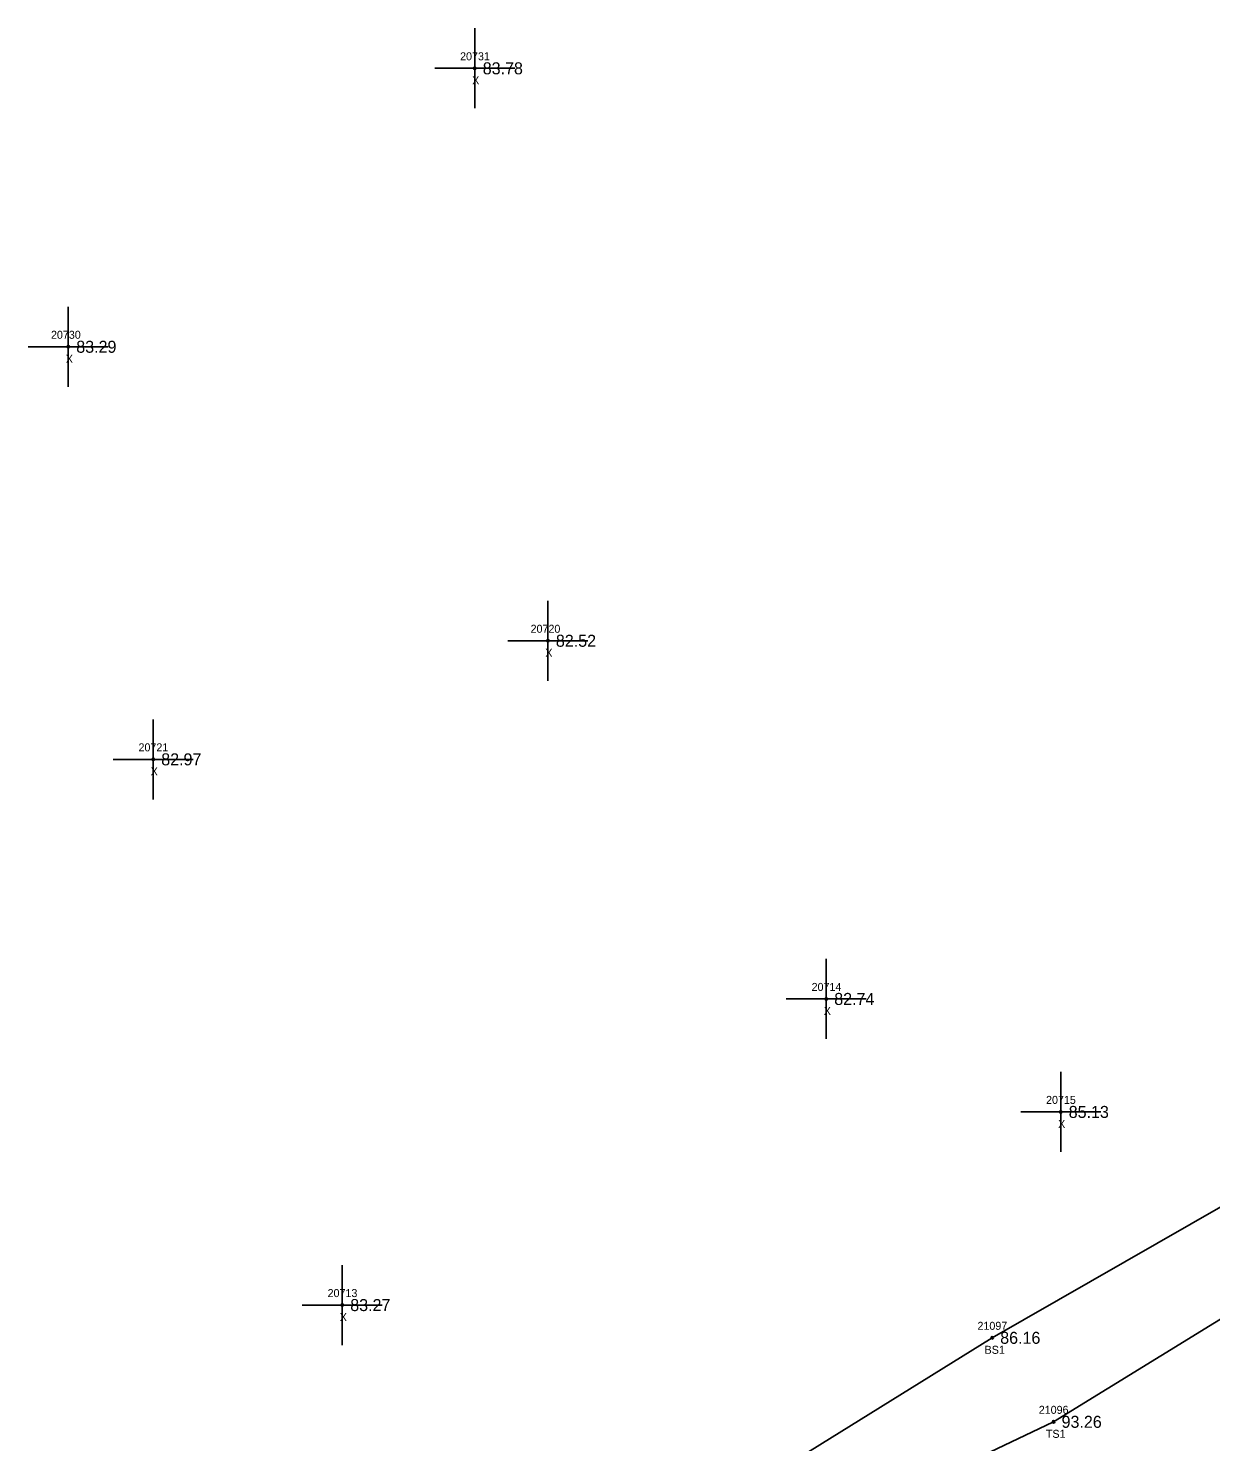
# Model space of a CAD drawing. Extents: x 2530197 to 2532051, y 935230 to 936631.
# Drawn here: x 2531110.5 to 2531258.3, y 936173.5 to 936350.2 of the extents above; entities that cross this region are included whole.
import ezdxf

# ---------------------------------------------------------------- set-up
doc = ezdxf.new("R2010")
doc.units = 0
for name, color, linetype in [('RD_DTM_BkLn2', 7, 'Continuous'), ('RD_DTM_BkLn_txCode', 7, 'Continuous'), ('RD_EX_Misc', 7, 'Continuous'), ('RD_EX_Misc_txCode', 7, 'Continuous'), ('RD_EX_TX_Misc_ELEV', 7, 'Continuous'), ('RD_SMD_Locator', 7, 'Continuous')]:
    doc.layers.add(name, color=color, linetype=linetype)

msp = doc.modelspace()

# ---------------------------------------------------------------- linework, layer by layer
at = {"layer": 'RD_DTM_BkLn2'}
for points in [[(2531151.41, 935999.3), (2531167.24, 936008.08), (2531181.24, 936018.79), (2531181.58, 936027.3), (2531178.12, 936073.45), (2531167.63, 936105.68), (2531166.35, 936111.09), (2531158.41, 936111.85), (2531152.62, 936122.31), (2531150.51, 936125.78), (2531152.42, 936137.74), (2531230.98, 936186.53), (2531313.57, 936233.84), (2531368.67, 936272.3), (2531431.6, 936307.72), (2531489.09, 936344.56)], [(2531153.52, 936135.49), (2531238.65, 936176.03), (2531319.12, 936225.52), (2531376.31, 936260.58), (2531439.07, 936295.88), (2531496.33, 936332.58)]]:
    msp.add_lwpolyline(points, dxfattribs=at)
at = {"layer": 'RD_EX_Misc'}
for p, q in [((2531166.31, 936340.18), (2531166.31, 936350.18)), ((2531161.31, 936345.18), (2531171.31, 936345.18)), ((2531115.51, 936305.38), (2531115.51, 936315.38)), ((2531110.51, 936310.38), (2531120.51, 936310.38)), ((2531175.45, 936268.64), (2531175.45, 936278.64)), ((2531170.45, 936273.64), (2531180.45, 936273.64)), ((2531126.13, 936253.82), (2531126.13, 936263.82)), ((2531121.13, 936258.82), (2531131.13, 936258.82)), ((2531210.24, 936223.88), (2531210.24, 936233.88)), ((2531205.24, 936228.88), (2531215.24, 936228.88)), ((2531239.54, 936209.76), (2531239.54, 936219.76)), ((2531234.54, 936214.76), (2531244.54, 936214.76)), ((2531149.75, 936185.62), (2531149.75, 936195.62)), ((2531144.75, 936190.62), (2531154.75, 936190.62))]:
    msp.add_line(p, q, dxfattribs=at)
at = {"layer": 'RD_SMD_Locator'}
for centre in [(2531166.31, 936345.18), (2531115.51, 936310.38), (2531175.45, 936273.64), (2531126.13, 936258.82), (2531210.24, 936228.88), (2531239.54, 936214.76), (2531149.75, 936190.62), (2531230.98, 936186.53), (2531238.65, 936176.03)]:
    msp.add_circle(centre, 0.15, dxfattribs=at)

# ---------------------------------------------------------------- texts
at = {"layer": 'RD_DTM_BkLn_txCode'}
for s, p in [('21097', (2531229.14, 936187.53)), ('BS1', (2531230.03, 936184.53)), ('21096', (2531236.8, 936177.03)), ('TS1', (2531237.69, 936174.03))]:
    msp.add_text(s, height=1, dxfattribs=at).set_placement(p)
at = {"layer": 'RD_EX_Misc_txCode'}
for s, p in [('20731', (2531164.48, 936346.18)), ('X', (2531165.99, 936343.18)), ('20730', (2531113.35, 936311.38)), ('X', (2531115.2, 936308.38)), ('20720', (2531173.29, 936274.64)), ('X', (2531175.13, 936271.64)), ('20721', (2531124.29, 936259.82)), ('X', (2531125.81, 936256.82)), ('20714', (2531208.41, 936229.88)), ('X', (2531209.93, 936226.88)), ('20715', (2531237.71, 936215.76)), ('X', (2531239.22, 936212.76)), ('20713', (2531147.92, 936191.62)), ('X', (2531149.44, 936188.62))]:
    msp.add_text(s, height=1, dxfattribs=at).set_placement(p)
at = {"layer": 'RD_EX_TX_Misc_ELEV'}
for s, p in [('83.78', (2531167.31, 936344.43)), ('83.29', (2531116.51, 936309.63)), ('82.52', (2531176.45, 936272.89)), ('82.97', (2531127.13, 936258.07)), ('82.74', (2531211.24, 936228.13)), ('85.13', (2531240.54, 936214.01)), ('83.27', (2531150.75, 936189.87)), ('86.16', (2531231.98, 936185.78)), ('93.26', (2531239.65, 936175.28))]:
    msp.add_text(s, height=1.5, dxfattribs=at).set_placement(p)

doc.saveas('drawing.dxf')
